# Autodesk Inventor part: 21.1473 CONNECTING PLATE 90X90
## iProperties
Created: 2007-01
Part Number: 21.1473 CONNECTING PLATE 90X90
Document SubType Name: Modeling
Designer: Andy Moles
Material: Aluminum-6061
Mass: 310.68 g
Surface Area: 227.426 cm^2
Volume: 114.642 cm^3
Density: 2.71 g/cm^3
Author: Andy Moles
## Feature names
1. Extrusion1
2. Hole1
3. Hole2
4. Fillet1
5. Hole3
6. Hole4
